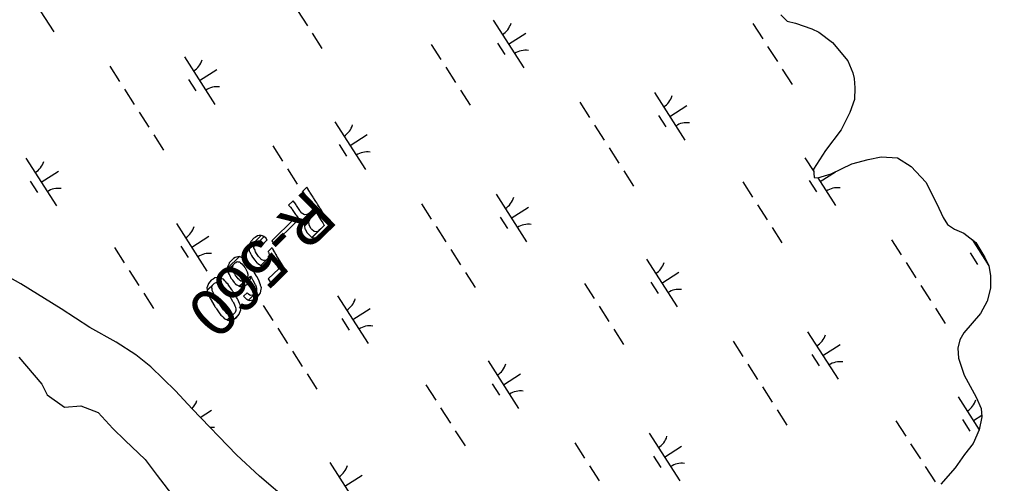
# Model space of a CAD drawing. Extents: x 3962991 to 3983549, y 181631 to 204078.
# Drawn here: x 3975197 to 3976056, y 193277 to 193687 of the extents above; entities that cross this region are included whole.
import ezdxf

# ---------------------------------------------------------------- set-up
doc = ezdxf.new("R2010")
doc.units = 0
for name, color, linetype in [('V-ANNO-MASK', 7, 'Continuous'), ('V-ANNO-MASK2', 7, 'Continuous'), ('V-RIVR-EDGE', 7, 'Continuous'), ('V-RIVR-RANG-IDEN', 7, 'Continuous'), ('V-WETL-SWMP', 7, 'Continuous')]:
    doc.layers.add(name, color=color, linetype=linetype)

msp = doc.modelspace()

# ---------------------------------------------------------------- linework, layer by layer
at = {"layer": 'V-ANNO-MASK2'}
for points in [[(3975452.45, 193537.35), (3975451.37, 193539.04), (3975447.7, 193535.44), (3975448.78, 193533.75), (3975449.01, 193533.39), (3975450.11, 193531.67), (3975450.44, 193531.15), (3975453.34, 193526.59), (3975453.7, 193526.02), (3975455.06, 193523.89), (3975455.62, 193523.02), (3975456.51, 193521.62), (3975457.15, 193520.61), (3975457.35, 193520.29), (3975457.52, 193520.02), (3975447.48, 193510.16), (3975449.12, 193510.15), (3975451.82, 193511.42), (3975450.54, 193509.67), (3975449.24, 193506.65), (3975449.27, 193506.28), (3975459.73, 193516.55), (3975459.84, 193516.39), (3975460.41, 193515.49), (3975461.36, 193514.01), (3975461.66, 193513.53), (3975463.55, 193510.56), (3975464.05, 193509.77), (3975465.46, 193507.57), (3975466.49, 193505.95), (3975466.7, 193505.61), (3975466.71, 193505.62), (3975466.79, 193505.47), (3975466.83, 193505.41), (3975456.04, 193494.8), (3975459.65, 193494.35), (3975463.08, 193495.98), (3975466.38, 193498.96), (3975472.84, 193505.32), (3975472.75, 193505.47), (3975472.07, 193506.55), (3975470.5, 193509), (3975470.46, 193509.07), (3975470.37, 193509.21), (3975470.15, 193509.55), (3975469.13, 193511.16), (3975467.72, 193513.37), (3975467.22, 193514.16), (3975465.33, 193517.13), (3975465.02, 193517.6), (3975464.08, 193519.09), (3975463.51, 193519.99), (3975463.4, 193520.15), (3975463.24, 193520.4), (3975462.56, 193521.48), (3975462.37, 193521.78), (3975461.83, 193522.63), (3975461.19, 193523.62), (3975461.02, 193523.9), (3975460.82, 193524.21), (3975460.18, 193525.22), (3975459.28, 193526.62), (3975458.73, 193527.5), (3975457.37, 193529.62), (3975457.01, 193530.2), (3975454.11, 193534.75), (3975453.78, 193535.27), (3975452.67, 193536.99)], [(3975440.46, 193525.58), (3975439.2, 193527.09), (3975435.19, 193523.16), (3975436.6, 193521.79), (3975436.87, 193521.47), (3975438.14, 193519.92), (3975438.49, 193519.41), (3975441.46, 193514.92), (3975441.83, 193514.36), (3975443.41, 193512.46), (3975444.06, 193511.67), (3975445.49, 193510.79), (3975446.51, 193510.16), (3975447.03, 193510.16), (3975447.48, 193510.16), (3975454.06, 193516.62), (3975451.93, 193514.97), (3975451.34, 193514.9), (3975449.43, 193514.66), (3975447.98, 193515.52), (3975447.07, 193516.05), (3975445.55, 193518.01), (3975445.14, 193518.54), (3975442.24, 193523.09), (3975441.89, 193523.6), (3975440.73, 193525.26)], [(3975454.42, 193511.07), (3975456.73, 193513.6), (3975449.27, 193506.28), (3975449.29, 193506.03), (3975449.4, 193504.68), (3975453.2, 193508.41)], [(3975441.97, 193508.5), (3975440.24, 193511.21), (3975420.4, 193491.72), (3975422.12, 193489.01)], [(3975453.46, 193506.25), (3975453.19, 193508.4), (3975449.4, 193504.68), (3975449.58, 193502.44), (3975449.87, 193501.95), (3975451.67, 193498.89), (3975452.14, 193498.08), (3975454.05, 193496.36), (3975455.45, 193495.11), (3975455.74, 193494.84), (3975455.95, 193494.82), (3975461.99, 193500.76), (3975461.42, 193500.42), (3975460.05, 193499.62), (3975457.75, 193499.99), (3975455.93, 193501.8), (3975455.29, 193502.44), (3975453.54, 193505.55)], [(3975405.67, 193494.72), (3975404.64, 193494.05), (3975401.97, 193491.09), (3975401.4, 193489.84), (3975400.28, 193487.39), (3975400.34, 193486.16), (3975410.93, 193496.56), (3975409.39, 193496.33), (3975407.76, 193496.09)], [(3975412.16, 193496.08), (3975410.93, 193496.56), (3975400.34, 193486.16), (3975400.41, 193484.54), (3975406.54, 193490.56), (3975408.32, 193491.66), (3975408.66, 193491.86), (3975409.64, 193491.78), (3975409.64, 193491.79), (3975409.76, 193491.78), (3975413.58, 193495.53), (3975413.49, 193495.56), (3975412.73, 193495.86), (3975412.64, 193495.9)], [(3975463.87, 193502.49), (3975461.99, 193500.75), (3975455.95, 193494.82), (3975456.04, 193494.8)], [(3975404.96, 193488.35), (3975406.54, 193490.56), (3975400.42, 193484.54), (3975400.44, 193483.92), (3975400.45, 193483.8), (3975400.49, 193482.8), (3975400.54, 193482.72), (3975400.81, 193482.2), (3975400.9, 193482.02), (3975401.67, 193480.53), (3975401.71, 193480.45), (3975402.6, 193478.73), (3975403.41, 193477.16), (3975405.33, 193474.68), (3975407.08, 193472.4), (3975407.2, 193472.24), (3975407.71, 193471.9), (3975408.13, 193471.62), (3975409.49, 193470.69), (3975409.77, 193470.5), (3975410.49, 193470.02), (3975410.49, 193470.02), (3975410.64, 193469.91), (3975415.74, 193474.92), (3975415.34, 193474.79), (3975413.59, 193474.25), (3975413.25, 193474.39), (3975411.65, 193475.08), (3975411.16, 193475.28), (3975410.75, 193475.73), (3975410.62, 193475.88), (3975408.69, 193477.99), (3975406.99, 193480.67), (3975406.06, 193482.12), (3975405.31, 193483.99), (3975405.28, 193484.06), (3975404.62, 193485.67), (3975404.66, 193485.98), (3975404.77, 193486.88), (3975404.79, 193487.02), (3975404.94, 193488.21)], [(3975414, 193495.15), (3975413.57, 193495.53), (3975409.76, 193491.78), (3975410.5, 193491.71), (3975410.66, 193491.6), (3975411.98, 193490.65), (3975412.04, 193490.6), (3975413.07, 193489.4), (3975416.38, 193492.66), (3975415.42, 193493.92), (3975415.37, 193493.97), (3975414.15, 193495.03)], [(3975420.75, 193485.55), (3975420.64, 193485.73), (3975417.2, 193482.34), (3975417.3, 193482.15), (3975417.57, 193481.58), (3975417.79, 193481.11), (3975418.04, 193479.1), (3975417.85, 193478.43), (3975417.85, 193478.44), (3975417.37, 193476.78), (3975415.74, 193474.91), (3975410.65, 193469.92), (3975410.93, 193469.72), (3975412.07, 193469.68), (3975420.25, 193477.73), (3975420.95, 193476.54), (3975421.22, 193476.09), (3975421.43, 193475.74), (3975426.51, 193467.14), (3975417.26, 193458.05), (3975419.45, 193454.62), (3975431.83, 193466.78), (3975429.75, 193470.32), (3975424.67, 193478.92), (3975424.46, 193479.27), (3975424.19, 193479.73), (3975423.49, 193480.91), (3975423.07, 193481.63), (3975422.89, 193481.93), (3975422.79, 193482.1), (3975422.35, 193482.85), (3975422.17, 193483.15), (3975421.32, 193484.58), (3975421.07, 193485.01)], [(3975386.66, 193476.04), (3975385.31, 193475.03), (3975382.85, 193472.3), (3975382.62, 193471.75), (3975382.62, 193471.76), (3975381.28, 193468.64), (3975381.36, 193467.57), (3975391.77, 193477.79), (3975390.3, 193477.5), (3975388.01, 193477.05)], [(3975392.96, 193477.26), (3975391.76, 193477.79), (3975381.36, 193467.57), (3975381.47, 193465.97), (3975388.03, 193472.41), (3975388.53, 193472.67), (3975389.85, 193473.36), (3975390.62, 193473.3), (3975390.87, 193473.28), (3975391.85, 193473.21), (3975392.51, 193472.69), (3975392.88, 193472.4), (3975393.96, 193471.54), (3975395.46, 193469.67), (3975395.78, 193469.27), (3975396.71, 193468.1), (3975396.81, 193467.92), (3975398.12, 193465.56), (3975398.72, 193464.47), (3975398.77, 193464.24), (3975398.77, 193464.24), (3975399.16, 193462.26), (3975399.31, 193461.5), (3975398.89, 193459.43), (3975398.84, 193459.18), (3975397.38, 193457.11), (3975391.73, 193451.57), (3975392.1, 193451.33), (3975392.23, 193451.33), (3975401.56, 193460.5), (3975401.59, 193460.47), (3975402.36, 193459.2), (3975402.87, 193458.36), (3975403.01, 193458.13), (3975403.77, 193456.87), (3975405.81, 193453.2), (3975405.85, 193453.09), (3975405.92, 193452.88), (3975406.59, 193451.05), (3975407.04, 193449.77), (3975407.04, 193449.57), (3975407, 193448.79), (3975406.92, 193447.09), (3975406.57, 193446.56), (3975405.48, 193444.88), (3975399.93, 193439.44), (3975400.05, 193439.38), (3975400.06, 193439.38), (3975400.76, 193439.07), (3975404.36, 193439.74), (3975410.38, 193445.64), (3975411, 193449.13), (3975411.22, 193450.35), (3975411.18, 193450.48), (3975411.02, 193450.93), (3975410.98, 193451.08), (3975410.57, 193452.3), (3975410.38, 193452.86), (3975410.34, 193453), (3975409.9, 193454.3), (3975409.28, 193456.17), (3975409.2, 193456.38), (3975409.15, 193456.48), (3975407.07, 193460.11), (3975406.33, 193461.39), (3975406.19, 193461.63), (3975405.7, 193462.49), (3975404.96, 193463.78), (3975404.94, 193463.81), (3975404.89, 193463.88), (3975404.65, 193464.25), (3975404.39, 193464.64), (3975404.32, 193464.76), (3975403.66, 193465.76), (3975403.29, 193466.32), (3975402.35, 193467.76), (3975402.24, 193467.93), (3975401.57, 193468.95), (3975400.11, 193471.17), (3975399.98, 193471.32), (3975399, 193472.43), (3975398.66, 193472.81), (3975397.07, 193474.59), (3975396.16, 193475.62), (3975395.84, 193475.96), (3975395.03, 193476.33), (3975394.3, 193476.65), (3975394.12, 193476.74), (3975393.55, 193476.99), (3975393.12, 193477.18)], [(3975386.57, 193470.75), (3975388.03, 193472.41), (3975381.47, 193465.97), (3975381.48, 193465.75)], [(3975386.19, 193469.76), (3975386.57, 193470.75), (3975381.48, 193465.75), (3975381.52, 193465.18), (3975381.57, 193464.42), (3975381.59, 193464.17), (3975381.94, 193463.47), (3975382.34, 193462.7), (3975382.55, 193462.26), (3975383.2, 193460.98), (3975384.33, 193458.73), (3975384.64, 193458.34), (3975385.56, 193457.16), (3975385.57, 193457.16), (3975385.69, 193457), (3975387.3, 193454.94), (3975388.04, 193453.99), (3975388.16, 193453.83), (3975389.63, 193452.9), (3975390.19, 193452.54), (3975391.22, 193451.89), (3975391.34, 193451.82), (3975391.73, 193451.57), (3975397.38, 193457.11), (3975395.77, 193456.16), (3975395.27, 193455.87), (3975393.81, 193456.1), (3975393.01, 193456.22), (3975391.72, 193457.32), (3975391.57, 193457.45), (3975390.65, 193458.22), (3975389.09, 193460.34), (3975388.97, 193460.5), (3975388.08, 193461.71), (3975387.84, 193462.18), (3975386.7, 193464.4), (3975386.04, 193465.68), (3975385.97, 193466.27), (3975385.83, 193467.29), (3975385.72, 193468.22), (3975385.68, 193468.45)], [(3975420.04, 193475.65), (3975420.25, 193477.73), (3975412.07, 193469.68), (3975413.91, 193469.63), (3975414.62, 193469.6), (3975416.05, 193470.46), (3975417.38, 193471.26), (3975417.39, 193471.26), (3975419.26, 193473.62), (3975419.6, 193474.49)], [(3975368.47, 193457.98), (3975366.97, 193457), (3975364.44, 193454.02), (3975364.12, 193453.14), (3975363.06, 193450.27), (3975363.22, 193448.85), (3975363.3, 193448), (3975369.51, 193454.1), (3975369.77, 193454.24), (3975371.2, 193454.97), (3975371.8, 193454.94), (3975372.31, 193454.93), (3975373.27, 193454.89), (3975374.2, 193454.26), (3975374.21, 193454.26), (3975375.7, 193453.25), (3975376.54, 193452.23), (3975377.41, 193451.16), (3975378.33, 193450.03), (3975378.42, 193449.91), (3975381.56, 193445.17), (3975381.94, 193444.61), (3975382.65, 193443.53), (3975382.97, 193442.99), (3975382.97, 193443), (3975385.72, 193438.42), (3975385.73, 193438.42), (3975385.95, 193438.06), (3975386.59, 193436.98), (3975387.07, 193435.92), (3975387.76, 193434.4), (3975388.37, 193433.05), (3975388.38, 193432.93), (3975388.55, 193431.53), (3975388.61, 193430.93), (3975388.68, 193430.31), (3975388.32, 193429.32), (3975388.32, 193429.32), (3975387.95, 193428.32), (3975386.59, 193426.84), (3975381.41, 193421.76), (3975382.16, 193421.42), (3975383.62, 193421.58), (3975385.84, 193421.83), (3975387.41, 193422.84), (3975391.71, 193427.06), (3975391.98, 193427.85), (3975392.97, 193430.77), (3975392.85, 193431.92), (3975392.76, 193432.9), (3975392.74, 193433.03), (3975392.68, 193433.6), (3975392.62, 193434.18), (3975392.55, 193434.8), (3975392.36, 193435.28), (3975391.89, 193436.37), (3975391.85, 193436.47), (3975391.28, 193437.85), (3975390.61, 193439.4), (3975390.04, 193440.37), (3975389.4, 193441.45), (3975389.18, 193441.82), (3975386.45, 193446.42), (3975386.11, 193446.93), (3975385.39, 193448), (3975385.01, 193448.56), (3975381.84, 193453.27), (3975381.75, 193453.4), (3975380.78, 193454.47), (3975379.85, 193455.48), (3975378.96, 193456.45), (3975377.77, 193457.75), (3975377.76, 193457.76), (3975376.69, 193458.25), (3975376, 193458.56), (3975375.65, 193458.72), (3975375.22, 193458.91), (3975374.75, 193459.13), (3975374.66, 193459.16), (3975374.01, 193459.46), (3975372.25, 193459.29), (3975370.18, 193459.09)], [(3975368.14, 193452.63), (3975369.51, 193454.1), (3975363.3, 193448), (3975363.31, 193447.89)], [(3975401.56, 193460.45), (3975401.56, 193460.5), (3975392.23, 193451.33), (3975392.28, 193451.33), (3975394.38, 193451.37), (3975395.76, 193451.38), (3975396.9, 193452.13), (3975398.63, 193453.26), (3975400.62, 193455.79), (3975400.81, 193456.34), (3975401.46, 193458.31)], [(3975367.76, 193451.59), (3975368.14, 193452.63), (3975363.31, 193447.89), (3975363.37, 193447.28), (3975363.44, 193446.73), (3975363.48, 193446.26), (3975363.78, 193445.57), (3975364.24, 193444.49), (3975364.25, 193444.48), (3975365, 193442.74), (3975365.55, 193441.44), (3975366.27, 193440.22), (3975367.02, 193438.93), (3975367.02, 193438.93), (3975367.1, 193438.79), (3975369.99, 193433.81), (3975370.38, 193433.26), (3975371.11, 193432.19), (3975371.46, 193431.69), (3975374.43, 193427.33), (3975374.67, 193426.99), (3975375.52, 193426.11), (3975376.28, 193425.32), (3975377.36, 193424.18), (3975378.32, 193423.19), (3975378.39, 193423.11), (3975379.47, 193422.63), (3975379.48, 193422.63), (3975379.94, 193422.42), (3975380.43, 193422.2), (3975380.87, 193422), (3975384.92, 193425.98), (3975384.29, 193426), (3975383.62, 193426.02), (3975382.96, 193426.05), (3975382, 193426.66), (3975381.91, 193426.71), (3975380.71, 193427.46), (3975379.67, 193428.65), (3975378.95, 193429.48), (3975378.15, 193430.4), (3975377.87, 193430.71), (3975374.92, 193435.09), (3975374.58, 193435.6), (3975373.85, 193436.67), (3975373.5, 193437.26), (3975370.56, 193442.2), (3975370.48, 193442.33), (3975369.72, 193443.61), (3975369.11, 193444.93), (3975368.51, 193446.2), (3975367.73, 193447.89), (3975367.72, 193447.9), (3975367.57, 193449.29), (3975367.47, 193450.18), (3975367.42, 193450.64)], [(3975399.93, 193444.51), (3975398.72, 193445.81), (3975395.56, 193442.71), (3975396.78, 193441.42), (3975397.63, 193440.52), (3975397.72, 193440.42), (3975398.24, 193440.19), (3975399.38, 193439.68), (3975399.51, 193439.62), (3975399.93, 193439.44), (3975405.48, 193444.89), (3975403.57, 193443.61), (3975403.36, 193443.6), (3975401.58, 193443.47), (3975401.12, 193443.76), (3975401, 193443.84)], [(3975410.1, 193445.28), (3975410.38, 193445.64), (3975404.36, 193439.74), (3975404.47, 193439.75), (3975407.67, 193442.13), (3975407.67, 193442.14)], [(3975386.28, 193426.69), (3975384.92, 193425.98), (3975380.87, 193422), (3975381.31, 193421.8), (3975381.41, 193421.76), (3975386.59, 193426.84)], [(3975389.08, 193423.92), (3975391.7, 193427.05), (3975387.41, 193422.84), (3975389.08, 193423.91)]]:
    msp.add_lwpolyline(points, close=True, dxfattribs=at)
at = {"layer": 'V-RIVR-EDGE'}
msp.add_lwpolyline([(3975196.88, 193388.8), (3975217.06, 193365.06), (3975221.81, 193355.56), (3975237.24, 193344.88), (3975251.49, 193346.06), (3975266.92, 193340.13), (3975279.98, 193325.88), (3975290.67, 193315.2), (3975308.48, 193298.57), (3975319.16, 193284.33), (3975334.6, 193264.15)], dxfattribs=at)
at = {"layer": 'V-WETL-SWMP'}
for p, q in [((3975200.72, 193718.4), (3975227.7, 193676.3)), ((3975443.22, 193695.34), (3975451.86, 193681.87)), ((3975616.22, 193686.68), (3975643.21, 193644.58)), ((3975845.78, 193683.82), (3975854.41, 193670.35)), ((3975456.18, 193675.13), (3975464.81, 193661.66)), ((3975629.72, 193665.63), (3975644.87, 193675.35)), ((3975561.32, 193665.38), (3975569.95, 193651.91)), ((3975619.98, 193666.52), (3975626.46, 193656.42)), ((3975858.73, 193663.62), (3975867.36, 193650.15)), ((3975343.17, 193654.45), (3975370.15, 193612.35)), ((3975277.29, 193645.97), (3975285.92, 193632.5)), ((3975356.66, 193633.4), (3975371.81, 193643.11)), ((3975574.27, 193645.18), (3975582.91, 193631.71)), ((3975871.68, 193643.41), (3975880.32, 193629.94)), ((3975346.93, 193634.29), (3975353.4, 193624.18)), ((3975290.24, 193625.77), (3975298.87, 193612.3)), ((3975587.22, 193624.97), (3975595.86, 193611.5)), ((3975758.67, 193622.73), (3975785.66, 193580.63)), ((3975692.79, 193614.25), (3975701.43, 193600.78)), ((3975772.16, 193601.68), (3975787.32, 193611.39)), ((3975303.19, 193605.56), (3975311.83, 193592.09)), ((3975762.43, 193602.57), (3975768.91, 193592.46)), ((3975476.19, 193596.9), (3975503.18, 193554.81)), ((3975705.74, 193594.05), (3975714.38, 193580.58)), ((3975316.14, 193585.36), (3975324.78, 193571.89)), ((3975489.68, 193575.86), (3975504.84, 193585.57)), ((3975421.29, 193575.61), (3975429.92, 193562.14)), ((3975479.95, 193576.74), (3975486.43, 193566.64)), ((3975718.7, 193573.84), (3975727.33, 193560.37)), ((3975203.13, 193564.67), (3975230.12, 193522.58)), ((3975891.7, 193565.18), (3975899.5, 193553.02)), ((3975216.63, 193543.63), (3975231.78, 193553.34)), ((3975434.24, 193555.4), (3975442.87, 193541.93)), ((3975731.65, 193553.64), (3975740.29, 193540.17)), ((3975905.19, 193544.14), (3975918.71, 193552.8)), ((3975206.89, 193544.51), (3975213.37, 193534.41)), ((3975836.79, 193543.89), (3975845.43, 193530.42)), ((3975895.46, 193545.02), (3975901.93, 193534.92)), ((3975903.15, 193547.32), (3975918.68, 193523.09)), ((3975447.19, 193535.2), (3975455.83, 193521.73)), ((3975618.64, 193532.95), (3975645.63, 193490.86)), ((3975552.76, 193524.48), (3975561.39, 193511.01)), ((3975849.74, 193523.68), (3975858.38, 193510.21)), ((3975632.13, 193511.91), (3975647.29, 193521.62)), ((3975336.16, 193507.13), (3975363.14, 193465.04)), ((3975622.4, 193512.79), (3975628.88, 193502.69)), ((3975565.71, 193504.27), (3975574.35, 193490.8)), ((3975862.7, 193503.48), (3975871.33, 193490.01)), ((3975349.65, 193486.08), (3975364.81, 193495.8)), ((3975968.26, 193492.76), (3975976.9, 193479.29)), ((3976039.54, 193492.82), (3976054.46, 193469.54)), ((3975281.25, 193485.83), (3975289.89, 193472.36)), ((3975339.92, 193486.97), (3975346.39, 193476.87)), ((3975578.67, 193484.07), (3975587.3, 193470.6)), ((3976037.9, 193481.07), (3976044.38, 193470.97)), ((3976047.64, 193480.19), (3976048.49, 193480.73)), ((3975751.66, 193475.41), (3975778.65, 193433.32)), ((3975981.22, 193472.55), (3975989.85, 193459.08)), ((3975294.21, 193465.63), (3975302.84, 193452.16)), ((3975591.62, 193463.86), (3975600.25, 193450.39)), ((3975765.16, 193454.36), (3975780.31, 193464.08)), ((3975696.76, 193454.11), (3975705.39, 193440.64)), ((3975755.42, 193455.25), (3975761.9, 193445.15)), ((3975307.16, 193445.42), (3975315.8, 193431.95)), ((3975994.17, 193452.35), (3976002.81, 193438.88)), ((3975478.61, 193443.18), (3975505.59, 193401.09)), ((3975412.73, 193434.7), (3975421.36, 193421.23)), ((3975492.1, 193422.13), (3975507.25, 193431.85)), ((3975709.71, 193433.91), (3975718.35, 193420.44)), ((3976007.12, 193432.15), (3976015.76, 193418.68)), ((3975482.37, 193423.02), (3975488.84, 193412.92)), ((3975425.68, 193414.5), (3975434.32, 193401.03)), ((3975722.67, 193413.7), (3975731.3, 193400.23)), ((3975894.11, 193411.46), (3975921.1, 193369.37)), ((3975828.23, 193402.98), (3975836.87, 193389.52)), ((3975438.63, 193394.3), (3975447.27, 193380.83)), ((3975907.61, 193390.41), (3975922.76, 193400.13)), ((3975611.63, 193385.64), (3975638.62, 193343.54)), ((3975897.87, 193391.3), (3975904.35, 193381.2)), ((3975841.19, 193382.78), (3975849.82, 193369.31)), ((3975451.59, 193374.09), (3975460.22, 193360.62)), ((3975625.13, 193364.59), (3975640.28, 193374.31)), ((3975556.73, 193364.34), (3975565.36, 193350.87)), ((3975615.39, 193365.48), (3975621.87, 193355.38)), ((3975854.14, 193362.58), (3975862.77, 193349.11)), ((3976027.14, 193353.92), (3976045.84, 193324.75)), ((3975357.23, 193335.67), (3975367.22, 193342.07)), ((3975569.68, 193344.14), (3975578.32, 193330.67)), ((3975867.09, 193342.37), (3975875.73, 193328.9)), ((3976030.9, 193333.76), (3976037.37, 193323.66)), ((3976040.63, 193332.87), (3976047.98, 193337.59)), ((3975972.23, 193332.62), (3975980.87, 193319.15)), ((3975582.63, 193323.93), (3975591.27, 193310.46)), ((3975754.08, 193321.69), (3975781.07, 193279.59)), ((3975688.2, 193313.21), (3975696.84, 193299.74)), ((3975767.57, 193300.64), (3975782.73, 193310.35)), ((3975985.19, 193312.42), (3975993.82, 193298.95)), ((3975757.84, 193301.53), (3975764.32, 193291.42)), ((3975471.6, 193295.86), (3975498.59, 193253.77)), ((3975701.15, 193293.01), (3975709.79, 193279.54)), ((3975998.14, 193292.21), (3976006.77, 193278.74)), ((3975485.09, 193274.82), (3975500.25, 193284.53))]:
    msp.add_line(p, q, dxfattribs=at)
for points in [[(3975870.51, 193691.36), (3975876.01, 193685.98), (3975883.29, 193684.25), (3975897.85, 193678.98), (3975903.93, 193676.03), (3975916.12, 193667.11), (3975929.61, 193650.95), (3975933.97, 193640.12), (3975935.23, 193635.3), (3975935.94, 193626.84), (3975935.45, 193616.56), (3975931.35, 193605.03), (3975923.67, 193589.83), (3975909.98, 193571.54), (3975899.3, 193555.1), (3975899.99, 193547.85), (3975903.02, 193547.28), (3975915.06, 193551.05), (3975933.09, 193559.72), (3975947.55, 193563.52), (3975959.01, 193566.07), (3975973.52, 193565.03), (3975985.7, 193557.31), (3975998.55, 193543.56), (3976008.45, 193524.33), (3976014.03, 193512.31), (3976017.73, 193506.31), (3976023.82, 193502.15), (3976032.32, 193498.62), (3976042.69, 193490.28), (3976050.7, 193477.08), (3976054.41, 193469.87), (3976055.73, 193460.82), (3976055.85, 193449.94), (3976052.97, 193438.42), (3976047.05, 193427.48), (3976032.14, 193410.38), (3976028.58, 193404.29), (3976026.86, 193397.02), (3976027.56, 193387.96), (3976032.58, 193372.91), (3976043.08, 193353.69), (3976047.43, 193343.47), (3976048.11, 193336.22), (3976045.83, 193324.71), (3976040.53, 193312.56), (3976032.79, 193302.8), (3976024.46, 193291.22), (3976011.94, 193276.57)], [(3975409.7, 193283.66), (3975389.18, 193302.53), (3975349.89, 193343.28), (3975335.37, 193359.23), (3975313.62, 193380.48), (3975300.36, 193391.07), (3975282.92, 193402.21), (3975259.48, 193415.08), (3975234.2, 193431.51), (3975198.71, 193453.79), (3975169.86, 193469.57)], [(3975435.64, 193261.27), (3975409.7, 193283.66)]]:
    msp.add_lwpolyline(points, dxfattribs=at)
for centre, start, end in [((3975615.01, 193689.01), 301.89187, 343.43553), ((3975644.82, 193642.51), 81.89186, 123.43552), ((3975341.95, 193656.78), 301.89187, 343.43553), ((3975371.77, 193610.27), 81.89186, 123.43552), ((3975757.46, 193625.06), 301.89187, 343.43553), ((3975474.98, 193599.24), 301.89187, 343.43553), ((3975787.27, 193578.55), 81.89186, 123.43552), ((3975504.79, 193552.73), 81.89186, 123.43552), ((3975201.92, 193567.01), 301.89187, 343.43553), ((3975231.73, 193520.5), 81.89186, 123.43552), ((3975617.43, 193535.29), 301.89187, 343.43553), ((3975920.3, 193521.01), 81.89186, 123.43552), ((3975647.24, 193488.78), 81.89186, 123.43552), ((3975334.94, 193509.46), 301.89187, 343.43553), ((3976032.93, 193503.57), 301.89187, 305.98143), ((3975364.76, 193462.96), 81.89186, 123.43552), ((3975750.45, 193477.75), 301.89187, 343.43553), ((3976062.75, 193457.06), 122.26738, 123.43552), ((3975780.26, 193431.24), 81.89186, 123.43552), ((3975477.39, 193445.51), 301.89187, 343.43553), ((3975507.21, 193399.01), 81.89186, 123.43552), ((3975892.9, 193413.79), 301.89187, 343.43553), ((3975922.71, 193367.29), 81.89186, 123.43552), ((3975610.42, 193387.97), 301.89187, 343.43553), ((3975640.23, 193341.47), 81.89186, 123.43552), ((3975337.36, 193355.74), 315.15455, 343.43553), ((3976025.92, 193356.25), 301.89187, 343.43553), ((3975367.18, 193309.23), 81.89186, 94.55834), ((3975752.87, 193324.02), 301.89187, 343.43553), ((3975470.39, 193298.2), 301.89187, 343.43553), ((3975782.68, 193277.51), 81.89186, 123.43552)]:
    msp.add_arc(centre, 17.62, start, end, dxfattribs=at)

# ---------------------------------------------------------------- texts
at = {"layer": 'V-ANNO-MASK'}
msp.add_text('R-560  ', height=41.5, rotation=224.48213, dxfattribs=at).set_placement((3975450.92, 193538.6))
at = {"layer": 'V-RIVR-RANG-IDEN'}
msp.add_text('R-560  ', height=41.5, rotation=224.48213, dxfattribs=at).set_placement((3975450.92, 193538.6))

doc.saveas('drawing.dxf')
